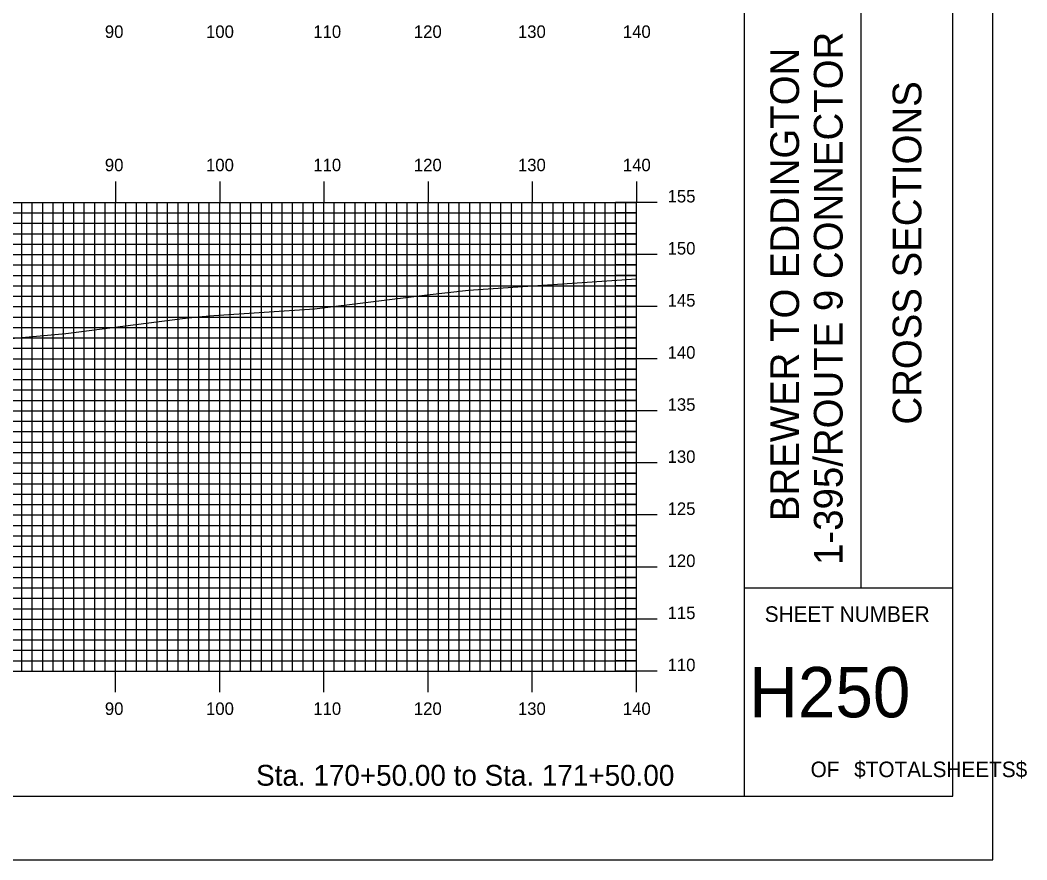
# Model space of a CAD drawing. Extents: x 1782647 to 1782990, y 442591 to 442811.
# Drawn here: x 1782893.8 to 1782990.4, y 442590.5 to 442671.2 of the extents above; entities that cross this region are included whole.
import ezdxf

# ---------------------------------------------------------------- set-up
doc = ezdxf.new("R2010")
doc.units = 0
for name, color, linetype in [('BORDER', 7, 'Continuous'), ('H_V ANNOTATION', 7, 'Continuous'), ('MAJOR', 7, 'Continuous'), ('MINOR', 7, 'Continuous'), ('PLOT BOUNDARY', 7, 'Continuous'), ('S_Roadway_Centerline', 7, 'Continuous')]:
    doc.layers.add(name, color=color, linetype=linetype)

msp = doc.modelspace()

# ---------------------------------------------------------------- linework, layer by layer
at = {"layer": 'BORDER'}
for p, q in [((1782963.347, 442596.665), (1782963.347, 442806.665)), ((1782974.529, 442616.671), (1782974.529, 442686.671)), ((1782974.529, 442616.671), (1782974.529, 442686.671)), ((1782963.347, 442616.671), (1782983.347, 442616.671)), ((1782963.347, 442616.671), (1782983.347, 442616.671))]:
    msp.add_line(p, q, dxfattribs=at)
msp.add_lwpolyline([(1782663.347, 442596.665), (1782983.347, 442596.665), (1782983.347, 442806.665), (1782663.347, 442806.665)], close=True, dxfattribs=at)
at = {"layer": 'MAJOR'}
for p, q in [((1782902.947, 442655.669), (1782902.947, 442653.665)), ((1782912.947, 442655.669), (1782912.947, 442653.665)), ((1782922.947, 442655.669), (1782922.947, 442653.665)), ((1782932.947, 442655.669), (1782932.947, 442653.665)), ((1782942.947, 442655.669), (1782942.947, 442653.665)), ((1782952.947, 442655.669), (1782952.947, 442653.665)), ((1782672.947, 442653.665), (1782952.947, 442653.665)), ((1782672.947, 442653.665), (1782952.947, 442653.665)), ((1782902.947, 442608.665), (1782902.947, 442653.665)), ((1782912.947, 442608.665), (1782912.947, 442653.665)), ((1782922.947, 442608.665), (1782922.947, 442653.665)), ((1782932.947, 442608.665), (1782932.947, 442653.665)), ((1782942.947, 442608.665), (1782942.947, 442653.665)), ((1782954.951, 442653.665), (1782950.943, 442653.665)), ((1782952.947, 442608.665), (1782952.947, 442653.665)), ((1782952.947, 442608.665), (1782952.947, 442653.665)), ((1782672.947, 442648.665), (1782952.947, 442648.665)), ((1782954.951, 442648.665), (1782950.943, 442648.665)), ((1782672.947, 442643.665), (1782952.947, 442643.665)), ((1782954.951, 442643.665), (1782950.943, 442643.665)), ((1782672.947, 442638.665), (1782952.947, 442638.665)), ((1782954.951, 442638.665), (1782950.943, 442638.665)), ((1782672.947, 442633.665), (1782952.947, 442633.665)), ((1782954.951, 442633.665), (1782950.943, 442633.665)), ((1782672.947, 442628.665), (1782952.947, 442628.665)), ((1782954.951, 442628.665), (1782950.943, 442628.665)), ((1782672.947, 442623.665), (1782952.947, 442623.665)), ((1782954.951, 442623.665), (1782950.943, 442623.665)), ((1782672.947, 442618.665), (1782952.947, 442618.665)), ((1782954.951, 442618.665), (1782950.943, 442618.665)), ((1782672.947, 442613.665), (1782952.947, 442613.665)), ((1782954.951, 442613.665), (1782950.943, 442613.665)), ((1782672.947, 442608.665), (1782952.947, 442608.665)), ((1782672.947, 442608.665), (1782952.947, 442608.665)), ((1782902.947, 442606.661), (1782902.947, 442608.665)), ((1782912.947, 442606.661), (1782912.947, 442608.665)), ((1782922.947, 442606.661), (1782922.947, 442608.665)), ((1782932.947, 442606.661), (1782932.947, 442608.665)), ((1782942.947, 442606.661), (1782942.947, 442608.665)), ((1782954.951, 442608.665), (1782950.943, 442608.665)), ((1782952.947, 442606.661), (1782952.947, 442608.665))]:
    msp.add_line(p, q, dxfattribs=at)
at = {"layer": 'MINOR'}
for p, q in [((1782893.947, 442608.665), (1782893.947, 442653.665)), ((1782894.947, 442608.665), (1782894.947, 442653.665)), ((1782895.947, 442608.665), (1782895.947, 442653.665)), ((1782896.947, 442608.665), (1782896.947, 442653.665)), ((1782897.947, 442608.665), (1782897.947, 442653.665)), ((1782898.947, 442608.665), (1782898.947, 442653.665)), ((1782899.947, 442608.665), (1782899.947, 442653.665)), ((1782900.947, 442608.665), (1782900.947, 442653.665)), ((1782901.947, 442608.665), (1782901.947, 442653.665)), ((1782903.947, 442608.665), (1782903.947, 442653.665)), ((1782904.947, 442608.665), (1782904.947, 442653.665)), ((1782905.947, 442608.665), (1782905.947, 442653.665)), ((1782906.947, 442608.665), (1782906.947, 442653.665)), ((1782907.947, 442608.665), (1782907.947, 442653.665)), ((1782908.947, 442608.665), (1782908.947, 442653.665)), ((1782909.947, 442608.665), (1782909.947, 442653.665)), ((1782910.947, 442608.665), (1782910.947, 442653.665)), ((1782911.947, 442608.665), (1782911.947, 442653.665)), ((1782913.947, 442608.665), (1782913.947, 442653.665)), ((1782914.947, 442608.665), (1782914.947, 442653.665)), ((1782915.947, 442608.665), (1782915.947, 442653.665)), ((1782916.947, 442608.665), (1782916.947, 442653.665)), ((1782917.947, 442608.665), (1782917.947, 442653.665)), ((1782918.947, 442608.665), (1782918.947, 442653.665)), ((1782919.947, 442608.665), (1782919.947, 442653.665)), ((1782920.947, 442608.665), (1782920.947, 442653.665)), ((1782921.947, 442608.665), (1782921.947, 442653.665)), ((1782923.947, 442608.665), (1782923.947, 442653.665)), ((1782924.947, 442608.665), (1782924.947, 442653.665)), ((1782925.947, 442608.665), (1782925.947, 442653.665)), ((1782926.947, 442608.665), (1782926.947, 442653.665)), ((1782927.947, 442608.665), (1782927.947, 442653.665)), ((1782928.947, 442608.665), (1782928.947, 442653.665)), ((1782929.947, 442608.665), (1782929.947, 442653.665)), ((1782930.947, 442608.665), (1782930.947, 442653.665)), ((1782931.947, 442608.665), (1782931.947, 442653.665)), ((1782933.947, 442608.665), (1782933.947, 442653.665)), ((1782934.947, 442608.665), (1782934.947, 442653.665)), ((1782935.947, 442608.665), (1782935.947, 442653.665)), ((1782936.947, 442608.665), (1782936.947, 442653.665)), ((1782937.947, 442608.665), (1782937.947, 442653.665)), ((1782938.947, 442608.665), (1782938.947, 442653.665)), ((1782939.947, 442608.665), (1782939.947, 442653.665)), ((1782940.947, 442608.665), (1782940.947, 442653.665)), ((1782941.947, 442608.665), (1782941.947, 442653.665)), ((1782943.947, 442608.665), (1782943.947, 442653.665)), ((1782944.947, 442608.665), (1782944.947, 442653.665)), ((1782945.947, 442608.665), (1782945.947, 442653.665)), ((1782946.947, 442608.665), (1782946.947, 442653.665)), ((1782947.947, 442608.665), (1782947.947, 442653.665)), ((1782948.947, 442608.665), (1782948.947, 442653.665)), ((1782949.947, 442608.665), (1782949.947, 442653.665)), ((1782950.947, 442608.665), (1782950.947, 442653.665)), ((1782951.947, 442608.665), (1782951.947, 442653.665)), ((1782672.947, 442652.665), (1782952.947, 442652.665)), ((1782952.947, 442652.665), (1782950.943, 442652.665)), ((1782672.947, 442651.665), (1782952.947, 442651.665)), ((1782952.947, 442651.665), (1782950.943, 442651.665)), ((1782672.947, 442650.665), (1782952.947, 442650.665)), ((1782952.947, 442650.665), (1782950.943, 442650.665)), ((1782672.947, 442649.665), (1782952.947, 442649.665)), ((1782952.947, 442649.665), (1782950.943, 442649.665)), ((1782672.947, 442647.665), (1782952.947, 442647.665)), ((1782952.947, 442647.665), (1782950.943, 442647.665)), ((1782672.947, 442646.665), (1782952.947, 442646.665)), ((1782952.947, 442646.665), (1782950.943, 442646.665)), ((1782672.947, 442645.665), (1782952.947, 442645.665)), ((1782952.947, 442645.665), (1782950.943, 442645.665)), ((1782672.947, 442644.665), (1782952.947, 442644.665)), ((1782952.947, 442644.665), (1782950.943, 442644.665)), ((1782672.947, 442642.665), (1782952.947, 442642.665)), ((1782952.947, 442642.665), (1782950.943, 442642.665)), ((1782672.947, 442641.665), (1782952.947, 442641.665)), ((1782952.947, 442641.665), (1782950.943, 442641.665)), ((1782672.947, 442640.665), (1782952.947, 442640.665)), ((1782952.947, 442640.665), (1782950.943, 442640.665)), ((1782672.947, 442639.665), (1782952.947, 442639.665)), ((1782952.947, 442639.665), (1782950.943, 442639.665)), ((1782672.947, 442637.665), (1782952.947, 442637.665)), ((1782952.947, 442637.665), (1782950.943, 442637.665)), ((1782672.947, 442636.665), (1782952.947, 442636.665)), ((1782952.947, 442636.665), (1782950.943, 442636.665)), ((1782672.947, 442635.665), (1782952.947, 442635.665)), ((1782952.947, 442635.665), (1782950.943, 442635.665)), ((1782672.947, 442634.665), (1782952.947, 442634.665)), ((1782952.947, 442634.665), (1782950.943, 442634.665)), ((1782672.947, 442632.665), (1782952.947, 442632.665)), ((1782952.947, 442632.665), (1782950.943, 442632.665)), ((1782672.947, 442631.665), (1782952.947, 442631.665)), ((1782952.947, 442631.665), (1782950.943, 442631.665)), ((1782672.947, 442630.665), (1782952.947, 442630.665)), ((1782952.947, 442630.665), (1782950.943, 442630.665)), ((1782672.947, 442629.665), (1782952.947, 442629.665)), ((1782952.947, 442629.665), (1782950.943, 442629.665)), ((1782672.947, 442627.665), (1782952.947, 442627.665)), ((1782952.947, 442627.665), (1782950.943, 442627.665)), ((1782672.947, 442626.665), (1782952.947, 442626.665)), ((1782952.947, 442626.665), (1782950.943, 442626.665)), ((1782672.947, 442625.665), (1782952.947, 442625.665)), ((1782952.947, 442625.665), (1782950.943, 442625.665)), ((1782672.947, 442624.665), (1782952.947, 442624.665)), ((1782952.947, 442624.665), (1782950.943, 442624.665)), ((1782672.947, 442622.665), (1782952.947, 442622.665)), ((1782952.947, 442622.665), (1782950.943, 442622.665)), ((1782672.947, 442621.665), (1782952.947, 442621.665)), ((1782952.947, 442621.665), (1782950.943, 442621.665)), ((1782672.947, 442620.665), (1782952.947, 442620.665)), ((1782952.947, 442620.665), (1782950.943, 442620.665)), ((1782672.947, 442619.665), (1782952.947, 442619.665)), ((1782952.947, 442619.665), (1782950.943, 442619.665)), ((1782672.947, 442617.665), (1782952.947, 442617.665)), ((1782952.947, 442617.665), (1782950.943, 442617.665)), ((1782672.947, 442616.665), (1782952.947, 442616.665)), ((1782952.947, 442616.665), (1782950.943, 442616.665)), ((1782672.947, 442615.665), (1782952.947, 442615.665)), ((1782952.947, 442615.665), (1782950.943, 442615.665)), ((1782672.947, 442614.665), (1782952.947, 442614.665)), ((1782952.947, 442614.665), (1782950.943, 442614.665)), ((1782672.947, 442612.665), (1782952.947, 442612.665)), ((1782952.947, 442612.665), (1782950.943, 442612.665)), ((1782672.947, 442611.665), (1782952.947, 442611.665)), ((1782952.947, 442611.665), (1782950.943, 442611.665)), ((1782672.947, 442610.665), (1782952.947, 442610.665)), ((1782952.947, 442610.665), (1782950.943, 442610.665)), ((1782672.947, 442609.665), (1782952.947, 442609.665)), ((1782952.947, 442609.665), (1782950.943, 442609.665))]:
    msp.add_line(p, q, dxfattribs=at)
at = {"layer": 'PLOT BOUNDARY'}
msp.add_lwpolyline([(1782647.16, 442590.547), (1782987.16, 442590.547), (1782987.16, 442810.547), (1782647.16, 442810.547)], close=True, dxfattribs=at)
at = {"layer": 'S_Roadway_Centerline'}
msp.add_lwpolyline([(1782886.179, 442639.988), (1782898.169, 442641.087), (1782909.362, 442642.529), (1782910.863, 442642.67), (1782912.389, 442642.798), (1782922.062, 442643.441), (1782932.875, 442644.802), (1782936.846, 442645.23), (1782952.947, 442646.342)], dxfattribs=at)

# ---------------------------------------------------------------- texts
at = {"layer": 'BORDER'}
for s, p in [('1-395/ROUTE 9 CONNECTOR', (1782972.75, 442618.865)), ('BREWER TO EDDINGTON', (1782968.57, 442623.074)), ('CROSS SECTIONS', (1782980.316, 442632.339)), ('CROSS SECTIONS', (1782980.316, 442632.339))]:
    msp.add_text(s, height=2.75575, rotation=90, dxfattribs=at).set_placement(p)
for s, height, p in [('SHEET NUMBER', 1.49054, (1782965.278, 442613.398)), ('SHEET NUMBER', 1.49054, (1782965.278, 442613.398)), ('H250', 4.8388, (1782963.786, 442604.23)), ('OF', 1.4905, (1782969.681, 442598.491)), ('OF', 1.4905, (1782969.681, 442598.491)), ('$TOTALSHEETS$', 1.49054, (1782973.86, 442598.491)), ('$TOTALSHEETS$', 1.49054, (1782973.86, 442598.491))]:
    msp.add_text(s, height=height, dxfattribs=at).set_placement(p)
at = {"layer": 'H_V ANNOTATION'}
for s, height, p in [('90', 1.2, (1782901.919, 442669.465)), ('100', 1.2, (1782911.63, 442669.465)), ('110', 1.2, (1782921.93, 442669.465)), ('120', 1.2, (1782931.588, 442669.465)), ('130', 1.2, (1782941.577, 442669.465)), ('140', 1.2, (1782951.652, 442669.465)), ('90', 1.2, (1782901.919, 442656.665)), ('100', 1.2, (1782911.63, 442656.665)), ('110', 1.2, (1782921.93, 442656.665)), ('120', 1.2, (1782931.588, 442656.665)), ('130', 1.2, (1782941.577, 442656.665)), ('140', 1.2, (1782951.652, 442656.665)), ('155', 1.2, (1782955.947, 442653.665)), ('150', 1.2, (1782955.947, 442648.665)), ('145', 1.2, (1782955.947, 442643.665)), ('140', 1.2, (1782955.947, 442638.665)), ('135', 1.2, (1782955.947, 442633.665)), ('130', 1.2, (1782955.947, 442628.665)), ('125', 1.2, (1782955.947, 442623.665)), ('120', 1.2, (1782955.947, 442618.665)), ('115', 1.2, (1782955.947, 442613.665)), ('110', 1.2, (1782955.947, 442608.665)), ('90', 1.2, (1782901.919, 442604.465)), ('100', 1.2, (1782911.63, 442604.465)), ('110', 1.2, (1782921.93, 442604.465)), ('120', 1.2, (1782931.588, 442604.465)), ('130', 1.2, (1782941.577, 442604.465)), ('140', 1.2, (1782951.652, 442604.465)), ('Sta. 170+50.00 to Sta. 171+50.00', 2.0004, (1782916.438, 442597.665))]:
    msp.add_text(s, height=height, dxfattribs=at).set_placement(p)

doc.saveas('drawing.dxf')
